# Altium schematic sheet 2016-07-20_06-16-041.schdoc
size 186 x 111 mm; SheetNumber: 1; SheetTotal: 1
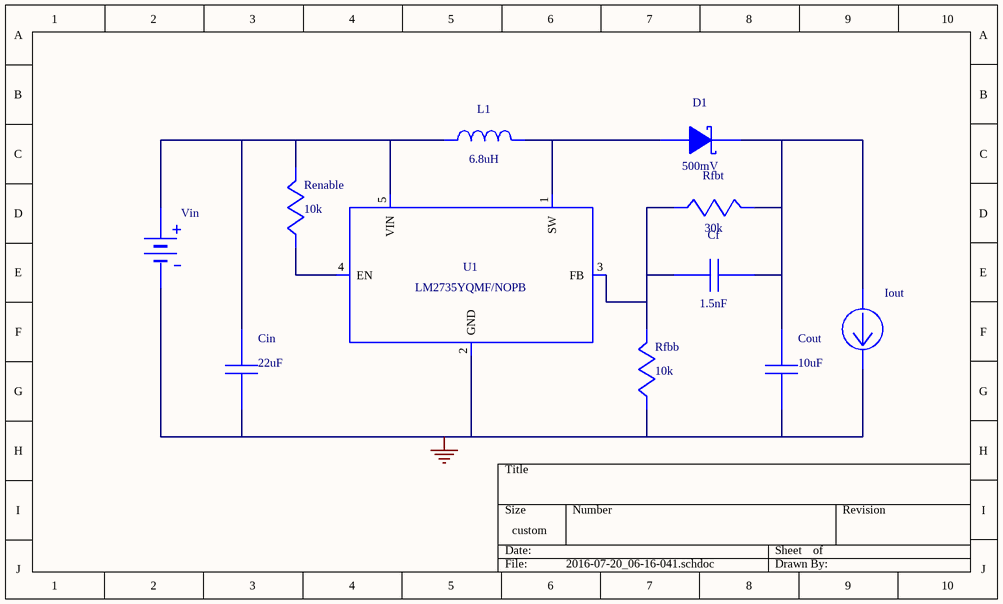
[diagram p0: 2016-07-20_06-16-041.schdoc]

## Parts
Cf  value 1.5nF  (hidden comment: CC0805KRX7R9BB152)
Cin  value 22uF  (hidden comment: GRM31CR61A226KE19L)
Cout  value 10uF  (hidden comment: GRM188R60J106ME47D)
D1  value 500mV  (hidden comment: B340A-13-F)
Iout  WB_CURRENT_LOAD  (value not drawn)
L1  value 6.8uH  (hidden comment: SRN6045-6R8Y)
Renable  value 10k  (hidden comment: CRCW040210K0FKED)
Rfbb  value 10k  (hidden comment: CRCW040210K0FKED)
Rfbt  value 30k  (hidden comment: RC0603FR-0730KL)
U1  LM2735YQMF/NOPB
Vin  WB_BATTERY  (value not drawn)

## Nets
0: Cin.2 Cout.2 Iout.2(-) Rfbb.2 U1.2(GND) Vin.2(-)
NetCf_1: Cf.1 Cout.1 D1.1(K) Iout.1(+) Rfbt.1
NetCf_2: Cf.2 Rfbb.1 Rfbt.2 U1.3(FB)
NetCin_1: Cin.1 L1.1 Renable.1 U1.5(VIN) Vin.1(+)
NetD1_2: D1.2(A) L1.2 U1.1(SW)
NetRenable_2: Renable.2 U1.4(EN)

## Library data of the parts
Cf = CC0805KRX7R9BB152: CC0805KRX7R9BB15; Manufacturer Name: Yageo America
Cin = GRM31CR61A226KE19L: GRM31CR61A226KE1; Manufacturer Name: MuRata
Cout = GRM188R60J106ME47D: GRM188R60J106ME4; Manufacturer Name: MuRata
D1 = B340A-13-F: Manufacturer Name: Diodes Inc.
L1 = SRN6045-6R8Y: Manufacturer Name: Bourns
Renable Rfbb = CRCW040210K0FKED: Manufacturer Name: Vishay-Dale
Rfbt = RC0603FR-0730KL: Manufacturer Name: Yageo America
U1 = LM2735YQMF/NOPB: Manufacturer Name: Texas Instruments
